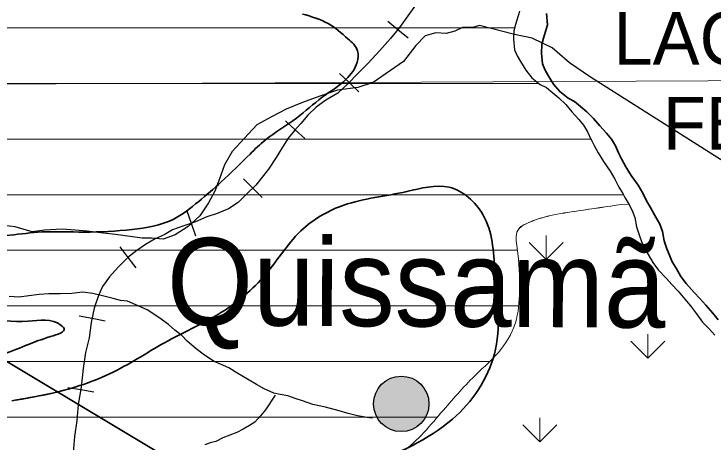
# Model space of a CAD drawing. Extents: x -10.5 to 30.8, y 18.4 to 58.7.
# Drawn here: x 8.628 to 11.148, y 42.761 to 44.305 of the extents above; entities that cross this region are included whole.
import ezdxf

# ---------------------------------------------------------------- set-up
doc = ezdxf.new("R2010")
doc.units = 0
doc.header["$LTSCALE"] = 0.08
doc.linetypes.add('DASH_DOUBLE_DOT', pattern=[9.2, 5, -1.2, 0.3, -1.2, 0.3, -1.2])
for name, color, linetype, lineweight in [('12', 7, 'Continuous', 25), ('16', 7, 'Continuous', 35), ('19', 7, 'DASH_DOUBLE_DOT', 53), ('28', 7, 'Continuous', 25), ('29', 7, 'Continuous', 13), ('4', 7, 'Continuous', 25), ('43', 7, 'Continuous', 13), ('47', 7, 'Continuous', 25), ('48', 7, 'Continuous', 35), ('52', 7, 'Continuous', 13), ('55', 7, 'Continuous', 25), ('57', 7, 'DASH_DOUBLE_DOT', 25), ('9', 7, 'Continuous', 25)]:
    doc.layers.add(name, color=color, linetype=linetype, lineweight=lineweight)

msp = doc.modelspace()

# ---------------------------------------------------------------- hatches: boundary and pattern name
at = {"layer": '4'}
msp.add_hatch(color=256, dxfattribs=at).paths.add_polyline_path([(10.12141, 42.90217, 1), (9.92194, 42.90217, 1)])

# ---------------------------------------------------------------- linework, layer by layer
at = {"layer": '12'}
for p, q in [((9.97309, 44.2796), (10.00971, 44.24942)), ((10.00971, 44.24942), (10.04632, 44.21924)), ((9.79955, 44.0904), (9.83409, 44.05788)), ((9.83409, 44.05788), (9.86864, 44.02535)), ((9.60442, 43.92035), (9.63947, 43.88836)), ((9.63947, 43.88836), (9.67452, 43.85637)), ((9.45395, 43.71216), (9.48727, 43.67837)), ((9.48727, 43.67837), (9.52058, 43.64459)), ((9.24947, 43.59658), (9.26499, 43.55174)), ((9.26499, 43.55174), (9.28051, 43.5069)), ((9.00915, 43.46672), (9.03783, 43.42891)), ((9.03783, 43.42891), (9.0665, 43.39111)), ((8.86226, 43.21921), (8.90881, 43.21002)), ((8.90881, 43.21002), (8.95536, 43.20083)), ((8.82094, 42.96137), (8.86775, 42.95356)), ((8.86775, 42.95356), (8.91455, 42.94575))]:
    msp.add_line(p, q, dxfattribs=at)
msp.add_lwpolyline([(10.07602, 44.34094), (10.04567, 44.29858), (10.01533, 44.25624), (9.98249, 44.21641), (9.94463, 44.1741), (9.90171, 44.12681), (9.86388, 44.08951), (9.83108, 44.05467), (9.79325, 44.01986), (9.75048, 43.99508), (9.71524, 43.97026), (9.68497, 43.94041), (9.65971, 43.91054), (9.637, 43.88565), (9.61426, 43.85827), (9.594, 43.82587), (9.57122, 43.78848), (9.54337, 43.74612), (9.49789, 43.68885), (9.4651, 43.65652), (9.43483, 43.62667), (9.3996, 43.60435), (9.35938, 43.58705), (9.32171, 43.57475), (9.2815, 43.55745), (9.23878, 43.54267), (9.19859, 43.52788), (9.1684, 43.51053), (9.13571, 43.4957), (9.10051, 43.47587), (9.07028, 43.45353), (9.03754, 43.4287), (9.00222, 43.39387), (8.97192, 43.35902), (8.94664, 43.32415), (8.93139, 43.29172), (8.91607, 43.2468), (8.90572, 43.19436), (8.89785, 43.13939), (8.88498, 43.08695), (8.87711, 43.02949), (8.86916, 42.96202), (8.85873, 42.89957), (8.85337, 42.84209), (8.84548, 42.78462), (8.84011, 42.72715)], dxfattribs=at)
msp.add_lwpolyline([(10.07602, 44.34094), (10.04567, 44.29858), (10.01533, 44.25624), (9.98249, 44.21641), (9.94463, 44.1741), (9.90171, 44.12681), (9.86388, 44.08951), (9.83108, 44.05467), (9.79325, 44.01986), (9.75048, 43.99508), (9.71524, 43.97026), (9.68497, 43.94041), (9.65971, 43.91054), (9.637, 43.88565), (9.61426, 43.85827), (9.594, 43.82587), (9.57122, 43.78848), (9.54337, 43.74612), (9.49789, 43.68885), (9.4651, 43.65652), (9.43483, 43.62667), (9.3996, 43.60435), (9.35938, 43.58705), (9.32171, 43.57475), (9.2815, 43.55745), (9.23878, 43.54267), (9.19859, 43.52788), (9.1684, 43.51053), (9.13571, 43.4957), (9.10051, 43.47587), (9.07028, 43.45353), (9.03754, 43.4287), (9.00222, 43.39387), (8.97192, 43.35902), (8.94664, 43.32415), (8.93139, 43.29172), (8.91607, 43.2468), (8.90572, 43.19436), (8.89785, 43.13939), (8.88498, 43.08695), (8.87711, 43.02949), (8.86916, 42.96202), (8.85873, 42.89957), (8.85337, 42.84209), (8.84548, 42.78462), (8.84011, 42.72715)], dxfattribs=at)
at = {"layer": '16'}
msp.add_line((10.13057, 42.13922), (3.60875, 46.04227), dxfattribs=at)
at = {"layer": '19'}
for centre, radius, start, end in [((-10.02586, 61.06832), 35.53871, 298.19382, 343.49395), ((-10.0428, 60.19451), 39.81815, 297.24377, 345.91847)]:
    msp.add_arc(centre, radius, start, end, dxfattribs=at)
at = {"layer": '28'}
for points in [[(10.30336, 44.26299), (10.27974, 44.25638), (10.24276, 44.25646), (10.21415, 44.24284), (10.18327, 44.2342), (10.1459, 44.2374), (10.10785, 44.22654), (10.07403, 44.19203), (10.03019, 44.13381), (9.92004, 44.05842), (9.86559, 44.0408), (9.7924, 44.0309), (9.72835, 44.00892), (9.66659, 43.98671), (9.60724, 43.96226), (9.55467, 43.9351), (9.50224, 43.90557), (9.41276, 43.81072), (9.38547, 43.76164), (9.36777, 43.71234), (9.35026, 43.6678), (9.32779, 43.62573), (9.29599, 43.57912), (9.25512, 43.53983), (9.20735, 43.51019), (9.16445, 43.49488), (9.12233, 43.49818), (9.08947, 43.4989), (8.99339, 43.51105), (8.93954, 43.51716), (8.89036, 43.52317), (8.84806, 43.52666), (8.8011, 43.53025), (8.73756, 43.52707), (8.69268, 43.52112), (8.63208, 43.53943), (8.56883, 43.54575)], [(11.2426, 43.73533), (10.70342, 44.07777), (10.62702, 44.12949), (10.5649, 44.18291), (10.49288, 44.21792), (10.4297, 44.23117), (10.30336, 44.26299)]]:
    msp.add_lwpolyline(points, dxfattribs=at)
at = {"layer": '29', "lineweight": 25}
for points in [[(10.30336, 44.26299), (10.27974, 44.25638), (10.24276, 44.25646), (10.21415, 44.24284), (10.18327, 44.2342), (10.1459, 44.2374), (10.10785, 44.22654), (10.07403, 44.19203), (10.03019, 44.13381), (9.92004, 44.05842), (9.86559, 44.0408), (9.7924, 44.0309), (9.72835, 44.00892), (9.66659, 43.98671), (9.60724, 43.96226), (9.55467, 43.9351), (9.50224, 43.90557), (9.41276, 43.81072), (9.38547, 43.76164), (9.36777, 43.71234), (9.35026, 43.6678), (9.32779, 43.62573), (9.29599, 43.57912), (9.25512, 43.53983), (9.20735, 43.51019), (9.16445, 43.49488), (9.12233, 43.49818), (9.08947, 43.4989), (8.99339, 43.51105), (8.93954, 43.51716), (8.89036, 43.52317), (8.84806, 43.52666), (8.8011, 43.53025), (8.73756, 43.52707), (8.69268, 43.52112), (8.63208, 43.53943), (8.56883, 43.54575)], [(11.2426, 43.73533), (10.70342, 44.07777), (10.62702, 44.12949), (10.5649, 44.18291), (10.49288, 44.21792), (10.4297, 44.23117), (10.30336, 44.26299)]]:
    msp.add_lwpolyline(points, dxfattribs=at)
at = {"layer": '4'}
msp.add_circle((10.02168, 42.90217), 0.09974, dxfattribs=at)
at = {"layer": '43'}
for p, q in [((7.15236, 44.2548), (10.42998, 44.2548)), ((7.15236, 44.2548), (10.42998, 44.2548)), ((7.37629, 44.0548), (10.51826, 44.0548)), ((7.37629, 44.0548), (10.51826, 44.0548)), ((7.04326, 43.8548), (10.70438, 43.8548)), ((7.04326, 43.8548), (10.70438, 43.8548)), ((5.81284, 43.6548), (10.82159, 43.6548)), ((5.81284, 43.6548), (10.82159, 43.6548)), ((10.84076, 43.62016), (10.81456, 43.61931)), ((10.84076, 43.62016), (10.81456, 43.61931)), ((10.54314, 43.42167), (10.5432, 43.50801)), ((10.54314, 43.42167), (10.5432, 43.50801)), ((10.54314, 43.42167), (10.48213, 43.48276)), ((10.54314, 43.42167), (10.48213, 43.48276)), ((10.54314, 43.42167), (10.60423, 43.48268)), ((10.54314, 43.42167), (10.60423, 43.48268)), ((4.40189, 43.4548), (10.43916, 43.4548)), ((4.40189, 43.4548), (10.43916, 43.4548)), ((4.36342, 43.2548), (10.44499, 43.2548)), ((4.36342, 43.2548), (10.44499, 43.2548)), ((10.90918, 43.06693), (10.90924, 43.15327)), ((10.90918, 43.06693), (10.90924, 43.15327)), ((10.90918, 43.06693), (10.84817, 43.12802)), ((10.90918, 43.06693), (10.84817, 43.12802)), ((10.90918, 43.06693), (10.97027, 43.12794)), ((10.90918, 43.06693), (10.97027, 43.12794)), ((5.8305, 43.0548), (10.33874, 43.0548)), ((5.8305, 43.0548), (10.33874, 43.0548)), ((5.99874, 42.8548), (10.15014, 42.8548)), ((5.99874, 42.8548), (10.15014, 42.8548)), ((10.52086, 42.76531), (10.52092, 42.85166)), ((10.52086, 42.76531), (10.52092, 42.85166)), ((10.52086, 42.76531), (10.45985, 42.82641)), ((10.52086, 42.76531), (10.45985, 42.82641)), ((10.52086, 42.76531), (10.58196, 42.82632)), ((10.52086, 42.76531), (10.58196, 42.82632))]:
    msp.add_line(p, q, dxfattribs=at)
for points in [[(10.52223, 44.05158), (10.49239, 44.07579), (10.47036, 44.10225), (10.45107, 44.13374), (10.43909, 44.15469), (10.42966, 44.17554), (10.42607, 44.21409), (10.42732, 44.24476), (10.43336, 44.26757), (10.44764, 44.31402), (10.44826, 44.31423), (10.44826, 44.31423)], [(10.70635, 43.8509), (10.70427, 43.855), (10.69249, 43.88106), (10.67804, 43.90467), (10.66092, 43.92582), (10.63632, 43.95239), (10.61427, 43.97885), (10.58957, 44.00286), (10.56722, 44.02166), (10.54488, 44.04045), (10.52223, 44.05158)], [(10.82705, 43.64484), (10.81958, 43.65845), (10.80513, 43.68206), (10.79088, 43.71078), (10.77408, 43.73961), (10.74978, 43.77384), (10.73051, 43.80532), (10.71617, 43.83149), (10.70635, 43.8509), (10.70635, 43.8509)], [(10.81456, 43.61931), (10.84076, 43.62016), (10.82705, 43.64484), (10.82705, 43.64484)], [(11.15076, 43.14879), (11.12862, 43.1727), (11.10647, 43.19661), (11.08453, 43.22563), (11.06261, 43.25465), (11.04302, 43.27846), (11.01853, 43.30758), (10.99638, 43.33149), (10.9767, 43.35274), (10.94718, 43.38463), (10.9277, 43.41099), (10.9109, 43.43981), (10.89645, 43.46342), (10.88712, 43.48683), (10.8778, 43.51024), (10.86867, 43.53875), (10.86232, 43.57229), (10.8531, 43.59826), (10.84076, 43.62016)], [(11.15076, 43.14879), (11.12862, 43.1727), (11.10647, 43.19661), (11.08453, 43.22563), (11.06261, 43.25465), (11.04302, 43.27846), (11.01853, 43.30758), (10.99638, 43.33149), (10.9767, 43.35274), (10.94718, 43.38463), (10.9277, 43.41099), (10.9109, 43.43981), (10.89645, 43.46342), (10.88712, 43.48683), (10.8778, 43.51024), (10.86867, 43.53875), (10.86232, 43.57229), (10.8531, 43.59826), (10.84076, 43.62016)]]:
    msp.add_lwpolyline(points, dxfattribs=at)
for points in [[(10.81456, 43.61931), (10.65863, 43.59662), (10.55853, 43.57938), (10.47365, 43.55116), (10.44122, 43.52627), (10.4386, 43.46385), (10.4477, 43.30721), (10.43244, 43.19314), (10.37039, 43.08595), (10.294, 43.01054), (10.17341, 42.8794), (10.02584, 42.72839), (9.75814, 42.5817), (9.56835, 42.42178), (9.44211, 42.28043), (9.38703, 42.21468), (9.33522, 42.10191), (9.29775, 41.95737), (9.26398, 41.77623), (9.16973, 41.64935), (9.00955, 41.57174), (8.8929, 41.53425), (8.70117, 41.45256), (8.66399, 41.42115)], [(10.81456, 43.61931), (10.65863, 43.59662), (10.55853, 43.57938), (10.47365, 43.55116), (10.44122, 43.52627), (10.4386, 43.46385), (10.4477, 43.30721), (10.43244, 43.19314), (10.37039, 43.08595), (10.294, 43.01054), (10.17341, 42.8794), (10.02584, 42.72839), (9.75814, 42.5817), (9.56835, 42.42178), (9.44211, 42.28043), (9.38703, 42.21468), (9.33522, 42.10191), (9.29775, 41.95737), (9.26398, 41.77623), (9.16973, 41.64935), (9.00955, 41.57174), (8.8929, 41.53425), (8.70117, 41.45256), (8.66399, 41.42115)], [(10.45217, 43.54031), (10.47365, 43.55116), (10.55853, 43.57938), (10.65863, 43.59662), (10.81456, 43.61931)], [(8.66399, 41.42115), (8.70117, 41.45256), (8.8929, 41.53425), (9.00955, 41.57174), (9.16973, 41.64935), (9.26398, 41.77623), (9.29775, 41.95737), (9.33522, 42.10191), (9.38703, 42.21468), (9.44211, 42.28043), (9.56835, 42.42178), (9.75814, 42.5817), (10.02584, 42.72839), (10.17341, 42.8794), (10.294, 43.01054), (10.37039, 43.08595), (10.43244, 43.19314), (10.4477, 43.30721), (10.4386, 43.46385), (10.44122, 43.52627), (10.45217, 43.54031)]]:
    msp.add_spline(points, degree=3, dxfattribs=at)
at = {"layer": '48'}
msp.add_lwpolyline([(11.16261, 43.20465), (11.14302, 43.22846), (11.11853, 43.25758), (11.09638, 43.28149), (11.0767, 43.30274), (11.04718, 43.33463), (11.0277, 43.36099), (11.0109, 43.38981), (10.99645, 43.41342), (10.98712, 43.43683), (10.9778, 43.46024), (10.96867, 43.48875), (10.96232, 43.52229), (10.9531, 43.54826), (10.93393, 43.58229), (10.91958, 43.60845), (10.90513, 43.63206), (10.89088, 43.66078), (10.87408, 43.68961), (10.84978, 43.72384), (10.83051, 43.75532), (10.81617, 43.78149), (10.80427, 43.805), (10.79249, 43.83106), (10.77804, 43.85467), (10.76092, 43.87582), (10.73632, 43.90239), (10.71427, 43.92885), (10.68957, 43.95286), (10.66722, 43.97166), (10.64488, 43.99045), (10.62223, 44.00158), (10.59239, 44.02579), (10.57036, 44.05225), (10.55107, 44.08373), (10.53909, 44.10469), (10.52966, 44.12554), (10.52607, 44.16409), (10.52732, 44.19476), (10.53336, 44.21757), (10.54814, 44.26564), (10.54466, 44.30674)], dxfattribs=at)
for points in [[(4.94245, 43.67205), (4.9801, 43.69674), (5.05866, 43.69913), (5.13743, 43.70673), (5.22143, 43.71413), (5.3979, 43.68175), (5.48081, 43.66314), (5.57219, 43.59734), (5.67945, 43.53617), (5.76323, 43.53838), (5.89076, 43.5859), (6.03527, 43.66408), (6.0627, 43.69435), (6.14801, 43.73297), (6.20305, 43.67369), (6.21609, 43.61069), (6.23542, 43.44848), (6.31657, 43.38826), (6.47628, 43.33042), (6.61119, 43.30474), (6.72108, 43.30601), (6.81596, 43.32344), (6.98158, 43.40607), (7.02884, 43.53463), (7.12831, 43.66131), (7.26238, 43.73986), (7.42124, 43.78626), (7.46152, 43.87339), (7.47831, 44.02388), (7.51033, 44.16341), (7.51493, 44.27266), (7.45795, 44.41017), (7.39506, 44.40722), (7.29887, 44.35857), (7.14216, 44.23915), (6.96588, 44.15169), (6.79851, 44.02744), (6.66182, 43.88647), (6.53516, 43.85975), (6.40635, 43.90606), (6.34696, 43.98634), (6.37811, 44.10506), (6.45319, 44.14925), (6.55592, 44.22893), (6.63623, 44.27294), (6.73199, 44.31118), (6.85017, 44.38509), (7.00622, 44.48891), (7.13575, 44.70829), (7.1364, 44.7239), (7.1162, 44.8653), (7.06532, 45.02344), (6.9361, 45.18438), (6.85082, 45.2708), (6.86542, 45.36927), (6.98838, 45.43259), (7.15159, 45.45799), (7.27693, 45.4535), (7.40359, 45.48021), (7.51676, 45.55951), (7.56336, 45.67246), (7.5314, 45.78302), (7.49725, 45.84156), (7.54688, 45.9023), (7.61977, 45.89448), (7.67525, 45.84559), (7.74074, 45.78593), (7.80929, 45.7991), (7.85479, 45.88604), (7.96731, 45.94973), (8.13596, 45.98015), (8.26762, 46.00148), (8.42082, 46.03766), (8.68066, 46.12211), (8.80385, 46.19063), (8.87524, 46.27143), (8.90682, 46.40056), (8.90404, 46.58301), (8.87558, 46.77681), (8.80706, 46.88869), (8.6502, 47.01415), (8.60082, 47.08366), (8.61279, 47.1197), (8.73163, 47.20922), (8.83283, 47.25247), (8.94644, 47.34218), (9.15734, 47.50655), (9.28446, 47.66871), (9.39026, 47.82122), (9.57595, 48.13237), (9.64669, 48.19757)], [(4.94245, 43.67205), (4.9801, 43.69674), (5.05866, 43.69913), (5.13743, 43.70673), (5.22143, 43.71413), (5.3979, 43.68175), (5.48081, 43.66314), (5.57219, 43.59734), (5.67945, 43.53617), (5.76323, 43.53838), (5.89076, 43.5859), (6.03527, 43.66408), (6.0627, 43.69435), (6.14801, 43.73297), (6.20305, 43.67369), (6.21609, 43.61069), (6.23542, 43.44848), (6.31657, 43.38826), (6.47628, 43.33042), (6.61119, 43.30474), (6.72108, 43.30601), (6.81596, 43.32344), (6.98158, 43.40607), (7.02884, 43.53463), (7.12831, 43.66131), (7.26238, 43.73986), (7.42124, 43.78626), (7.46152, 43.87339), (7.47831, 44.02388), (7.51033, 44.16341), (7.51493, 44.27266), (7.45795, 44.41017), (7.39506, 44.40722), (7.29887, 44.35857), (7.14216, 44.23915), (6.96588, 44.15169), (6.79851, 44.02744), (6.66182, 43.88647), (6.53516, 43.85975), (6.40635, 43.90606), (6.34696, 43.98634), (6.37811, 44.10506), (6.45319, 44.14925), (6.55592, 44.22893), (6.63623, 44.27294), (6.73199, 44.31118), (6.85017, 44.38509), (7.00622, 44.48891), (7.13575, 44.70829), (7.1364, 44.7239), (7.1162, 44.8653), (7.06532, 45.02344), (6.9361, 45.18438), (6.85082, 45.2708), (6.86542, 45.36927), (6.98838, 45.43259), (7.15159, 45.45799), (7.27693, 45.4535), (7.40359, 45.48021), (7.51676, 45.55951), (7.56336, 45.67246), (7.5314, 45.78302), (7.49725, 45.84156), (7.54688, 45.9023), (7.61977, 45.89448), (7.67525, 45.84559), (7.74074, 45.78593), (7.80929, 45.7991), (7.85479, 45.88604), (7.96731, 45.94973), (8.13596, 45.98015), (8.26762, 46.00148), (8.42082, 46.03766), (8.68066, 46.12211), (8.80385, 46.19063), (8.87524, 46.27143), (8.90682, 46.40056), (8.90404, 46.58301), (8.87558, 46.77681), (8.80706, 46.88869), (8.6502, 47.01415), (8.60082, 47.08366), (8.61279, 47.1197), (8.73163, 47.20922), (8.83283, 47.25247), (8.94644, 47.34218), (9.15734, 47.50655), (9.28446, 47.66871), (9.39026, 47.82122), (9.57595, 48.13237), (9.64669, 48.19757)], [(9.66599, 44.30485), (9.75868, 44.27027), (9.82961, 44.21562), (9.86441, 44.17269), (9.86266, 44.13107), (9.82348, 44.06995), (9.73707, 44.00532), (9.64501, 43.93047), (9.53183, 43.85117), (9.47742, 43.80102), (9.37381, 43.70054), (9.29241, 43.63052), (9.20078, 43.56607), (9.0528, 43.52971), (8.8798, 43.52028), (8.72813, 43.52052), (8.61258, 43.50904), (8.42391, 43.50018), (8.26723, 43.5058), (8.10033, 43.517), (7.99131, 43.53655), (7.85031, 43.54161), (7.7452, 43.52975), (7.63878, 43.48668), (7.57261, 43.40569), (7.47422, 43.30502), (7.36693, 43.24114), (7.33037, 43.24245), (7.29578, 43.29059), (7.27251, 43.35915), (7.26557, 43.44277), (7.24427, 43.55815), (7.22579, 43.61613), (7.21012, 43.61669), (7.19858, 43.59106), (7.19683, 43.54944), (7.19464, 43.49741), (7.1918, 43.42978), (7.18939, 43.37256), (7.18698, 43.31533), (7.16237, 43.22764), (7.1504, 43.1916), (7.12253, 43.15092), (7.03025, 43.07087), (6.94994, 43.02686), (6.79717, 43.00108), (6.67859, 43.04181), (6.59243, 43.10743), (6.53826, 43.18752), (6.47234, 43.23678), (6.41924, 43.21785), (6.37593, 43.18293), (6.37418, 43.14131), (6.4229, 43.0562), (6.44551, 42.97202), (6.50837, 42.84993), (6.57039, 42.83208), (6.62805, 42.83522), (6.70705, 42.84801), (6.8646, 42.8632), (6.97993, 42.86948), (7.0548, 42.90847), (7.16209, 42.97235), (7.24371, 43.04758), (7.34144, 43.13264), (7.51294, 43.23069), (7.62524, 43.28918), (7.68791, 43.28693), (7.80803, 43.28262), (7.95839, 43.25117), (8.08307, 43.23106), (8.17163, 43.22267), (8.29698, 43.21817), (8.51632, 43.2103), (8.678, 43.19929), (8.79768, 43.18457), (8.80769, 43.17379), (8.75937, 43.14426), (8.67972, 43.11586), (8.58941, 43.08263), (8.52086, 43.06946), (8.38964, 43.05854), (8.26408, 43.05784), (8.18574, 43.06065), (8.08651, 43.06421), (7.98707, 43.06257), (7.87652, 43.0457), (7.6765, 42.89136), (7.58922, 42.80592), (7.42228, 42.69208), (7.26558, 42.57266)], [(9.66599, 44.30485), (9.75868, 44.27027), (9.82961, 44.21562), (9.86441, 44.17269), (9.86266, 44.13107), (9.82348, 44.06995), (9.73707, 44.00532), (9.64501, 43.93047), (9.53183, 43.85117), (9.47742, 43.80102), (9.37381, 43.70054), (9.29241, 43.63052), (9.20078, 43.56607), (9.0528, 43.52971), (8.8798, 43.52028), (8.72813, 43.52052), (8.61258, 43.50904), (8.42391, 43.50018), (8.26723, 43.5058), (8.10033, 43.517), (7.99131, 43.53655), (7.85031, 43.54161), (7.7452, 43.52975), (7.63878, 43.48668), (7.57261, 43.40569), (7.47422, 43.30502), (7.36693, 43.24114), (7.33037, 43.24245), (7.29578, 43.29059), (7.27251, 43.35915), (7.26557, 43.44277), (7.24427, 43.55815), (7.22579, 43.61613), (7.21012, 43.61669), (7.19858, 43.59106), (7.19683, 43.54944), (7.19464, 43.49741), (7.1918, 43.42978), (7.18939, 43.37256), (7.18698, 43.31533), (7.16237, 43.22764), (7.1504, 43.1916), (7.12253, 43.15092), (7.03025, 43.07087), (6.94994, 43.02686), (6.79717, 43.00108), (6.67859, 43.04181), (6.59243, 43.10743), (6.53826, 43.18752), (6.47234, 43.23678), (6.41924, 43.21785), (6.37593, 43.18293), (6.37418, 43.14131), (6.4229, 43.0562), (6.44551, 42.97202), (6.50837, 42.84993), (6.57039, 42.83208), (6.62805, 42.83522), (6.70705, 42.84801), (6.8646, 42.8632), (6.97993, 42.86948), (7.0548, 42.90847), (7.16209, 42.97235), (7.24371, 43.04758), (7.34144, 43.13264), (7.51294, 43.23069), (7.62524, 43.28918), (7.68791, 43.28693), (7.80803, 43.28262), (7.95839, 43.25117), (8.08307, 43.23106), (8.17163, 43.22267), (8.29698, 43.21817), (8.51632, 43.2103), (8.678, 43.19929), (8.79768, 43.18457), (8.80769, 43.17379), (8.75937, 43.14426), (8.67972, 43.11586), (8.58941, 43.08263), (8.52086, 43.06946), (8.38964, 43.05854), (8.26408, 43.05784), (8.18574, 43.06065), (8.08651, 43.06421), (7.98707, 43.06257), (7.87652, 43.0457), (7.6765, 42.89136), (7.58922, 42.80592), (7.42228, 42.69208), (7.26558, 42.57266)], [(8.61982, 42.91313), (8.76651, 42.94081), (8.98413, 43.01636), (9.1824, 43.12908), (9.37501, 43.23158), (9.53237, 43.3666), (9.67015, 43.53359), (9.81488, 43.61697), (10.04186, 43.66614), (10.19419, 43.68151), (10.31559, 43.58337), (10.35928, 43.3786), (10.35725, 43.08169), (10.20617, 42.84745), (9.90605, 42.67586), (9.60049, 42.49927), (9.36326, 42.33063), (9.27901, 42.19298), (9.27354, 42.06293), (9.26478, 41.85483), (9.17531, 41.71737), (9.04147, 41.64402), (8.88173, 41.57681), (8.74441, 41.54527), (8.70698, 41.52577)], [(8.63493, 42.91598), (8.76651, 42.94081), (8.98413, 43.01636), (9.1824, 43.12908), (9.37501, 43.23158), (9.53237, 43.3666), (9.67015, 43.53359), (9.81488, 43.61697), (10.04186, 43.66614), (10.19419, 43.68151), (10.31559, 43.58337), (10.35928, 43.3786), (10.35725, 43.08169), (10.20617, 42.84745), (9.90605, 42.67586), (9.60049, 42.49927), (9.36326, 42.33063), (9.27901, 42.19298), (9.27354, 42.06293), (9.26478, 41.85483), (9.17531, 41.71737), (9.04147, 41.64402), (8.88173, 41.57681), (8.74441, 41.54527), (8.70698, 41.52577)]]:
    msp.add_spline(points, degree=3, dxfattribs=at)
at = {"layer": '52'}
msp.add_lwpolyline([(-9.61515, 43.9701), (10.09299, 44.05995), (15.25486, 44.08411), (20.41679, 44.0914), (25.57871, 44.0818), (29.5768, 44.0613)], dxfattribs=at)
at = {"layer": '55'}
for points in [[(10.44764, 44.31402), (10.43336, 44.26757), (10.42732, 44.24476), (10.42607, 44.21409), (10.42966, 44.17554), (10.43909, 44.15469), (10.45107, 44.13374), (10.47036, 44.10225), (10.49239, 44.07579), (10.52223, 44.05158)], [(10.52223, 44.05158), (10.54488, 44.04045), (10.56722, 44.02166), (10.58957, 44.00286), (10.61427, 43.97885), (10.63632, 43.95239), (10.66092, 43.92582), (10.67804, 43.90467), (10.69249, 43.88106), (10.70427, 43.855), (10.70635, 43.8509)], [(10.70635, 43.8509), (10.71617, 43.83149), (10.73051, 43.80532), (10.74978, 43.77384), (10.77408, 43.73961), (10.79088, 43.71078), (10.80513, 43.68206), (10.81958, 43.65845), (10.82705, 43.64484), (10.82705, 43.64484), (10.84076, 43.62016)], [(10.84076, 43.62016), (10.8531, 43.59826), (10.86232, 43.57229), (10.86867, 43.53875), (10.8778, 43.51024), (10.88712, 43.48683), (10.89645, 43.46342), (10.9109, 43.43981), (10.9277, 43.41099), (10.94718, 43.38463), (10.9767, 43.35274), (10.99638, 43.33149), (11.01853, 43.30758), (11.04302, 43.27846), (11.06261, 43.25465), (11.08453, 43.22563), (11.10647, 43.19661), (11.12862, 43.1727), (11.15076, 43.14879)]]:
    msp.add_lwpolyline(points, dxfattribs=at)
at = {"layer": '9'}
for points in [[(9.91849, 42.85089), (9.90622, 42.85167), (9.86365, 42.85939), (9.83111, 42.86706), (9.79859, 42.87723), (9.74854, 42.88999), (9.70349, 42.90022), (9.66596, 42.91291), (9.64346, 42.92053), (9.61343, 42.93069), (9.5859, 42.93583), (9.56336, 42.94094), (9.52837, 42.95613), (9.50089, 42.97127), (9.46843, 42.99144), (9.43347, 43.01162), (9.40101, 43.03179), (9.371, 43.04445), (9.34852, 43.05456), (9.31356, 43.07724), (9.28363, 43.0999), (9.25121, 43.12757), (9.23129, 43.14767), (9.20634, 43.1678), (9.18391, 43.18792), (9.14898, 43.2131), (9.10654, 43.24082), (9.06655, 43.25853), (9.03655, 43.27119), (9.01149, 43.27381), (8.98398, 43.28146), (8.95144, 43.28913), (8.91139, 43.29933), (8.87382, 43.30452), (8.8362, 43.29972), (8.79357, 43.29744), (8.75346, 43.29764), (8.71835, 43.29532), (8.68073, 43.29052), (8.6456, 43.2857), (8.61052, 43.28838)], [(9.56736, 42.93391), (9.53291, 42.8811), (9.51522, 42.85869), (9.49503, 42.83629), (9.4749, 42.82389), (9.45227, 42.8115), (9.42963, 42.79912), (9.4045, 42.78925), (9.37937, 42.77938), (9.35422, 42.767), (9.33414, 42.76211), (9.31404, 42.75471)]]:
    msp.add_lwpolyline(points, dxfattribs=at)

# ---------------------------------------------------------------- texts
at = {"layer": '47'}
for s, p in [('LAGOA', (10.78572, 44.12232)), ('FEIA', (10.96373, 43.81687))]:
    msp.add_text(s, height=0.1896, dxfattribs=at).set_placement(p)
at = {"layer": '57', "width": 0.95}
msp.add_text('Quissamã', height=0.314, rotation=359.682, dxfattribs=at).set_placement((9.1772, 43.18584))

doc.saveas('drawing.dxf')
